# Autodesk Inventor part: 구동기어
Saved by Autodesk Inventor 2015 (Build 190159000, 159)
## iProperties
Created: 2025-11
Part Number: 구동기어
Material: 일반
Document SubType Name: Modeling
Designer: user
Density: 1 g/cm^3
Appearance: 기본값
Author: user
Author: jhkim
Creation Date: 2025-10-31
Sending System: Autodesk Inventor 2026
Preprocessor: ST-DEVELOPER v20.1
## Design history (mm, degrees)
node "구동기어1"
node "솔리드1"
node "기준1"
